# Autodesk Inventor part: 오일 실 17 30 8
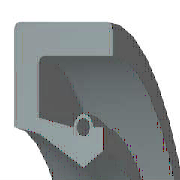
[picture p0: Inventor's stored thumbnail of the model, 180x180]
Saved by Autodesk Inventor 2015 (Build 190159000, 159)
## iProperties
Created: 2012-02
Part Number: 오일 실 17 30 8
Material: 고무
Description: 오일-실
Document SubType Name: Modeling
Standard: KS B 2804
Designer: mduedu
Standards Organization: KS
Language: ko-KR
Size Designation: S - 17 30 8
Categories: <MemberInstance><Categories><Category DisplayName="샤프트 부품" InternalName="7f7aeb1f-a693-4053-b835-cee3144e0d98" Mnemonic="SHFT"><Category DisplayName="실링" Intern
Density: 0.93 g/cm^3
Appearance: 고무 - 검은색 - 버전 1.1
Mass: 1.6913 g
Surface Area: 28.0102 cm^2
Volume: 1.81861 cm^3
IsCustomPart: 1
Author: mduedu
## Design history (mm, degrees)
revolve "본체" stored, may be unused: angle "d17" = 90 deg
revolve "스프링1" stored, may be unused: angle "d18" = 90 deg
body "Solid1"
sketch "스케치1"
  geometry: L1 (0, 15)-(8, 15); L2 (8, 15)-(8, 13.75); L3 (8, 13.75)-(1.75, 13.75); L4 (0, 15)-(0, 10.6); L5 (0, 10.6)-(1.75, 10.25); L6 (1.75, 10.25)-(4.9, 8.5); L7 (4.9, 8.5)-(0, 8.5); L8 (6.3, 9.375)-(6.3, 10.6); L9 (0, 0)-(9.586, 0) reference; L10 (4.9, 8.5)-(6.3, 9.375); L11 (0, 18)-(0, -3) reference; L12 (-1.917, 0)-(11.503, 0) reference; L13 (4.2, 10.6)-(1.75, 11.09); L14 (1.75, 11.09)-(1.75, 13.75); L15 (6.3, 10.6)-(5.6, 10.6); C1 r 0.455 at (4.9, 10.6); A1 r 0.7 centre (4.9, 10.6) between (5.6, 10.6) and (4.2, 10.6)
  constraints: 26 end point, 5 horizontal alignment, 4 perpendicular, 2 centre point, 2 collinear, 2 horizontal, 2 parallel, 2 point on circle, 2 point on line, 2 vertical alignment, 1 coincident
  dimensions: "d0" = 30 diameter of L1 L9 (= SD2); "d1" = 18.75 diameter of L8.start L9 (= ABDM); "d2" = 1.25 distance of L1.end L2.end (computed from SD); "d3" = 0.91 diameter of C1 (= SPDI); "d4" = 1.4 diameter of A1 (= SPDA); "d5" = 17 diameter of L6.end L9 (= NND); "d6" = 20.5 diameter of L5.end L9 (= TKDM); "d7" = 21.2 diameter of L4.end L9 (= HLDM); "d8" = 4.9 distance from line of C1.centre L4 (= SPDST); "d9" = 6.3 distance between parallel lines of L8 L4 (= SDI); "d10" = 8 distance between parallel lines of L2 L4 (= SWDT); "d12" = 1.75 distance between parallel lines of L14 L4 (= SD)
fillet "모깎기1" dims "d11" = 0.3 (= RR)
other parameters: "SD2" = 30 [user parameter; used in 1 equation term], "SWDT" = 8 [user parameter; used in 1 equation term], "RR" = 0.3 [user parameter; used in 1 equation term], "SD" = 1.75 [user parameter; used in 2 equation terms], "NND" = 17 [user parameter; used in 1 equation term], "SPDA" = 1.4 [user parameter; used in 1 equation term], "SPDI" = 0.91 [user parameter; used in 1 equation term], "TKDM" = 20.5 [user parameter; used in 1 equation term], "HLDM" = 21.2 [user parameter; used in 1 equation term], "ABDM" = 18.75 [user parameter; used in 1 equation term], "SDI" = 6.3 [user parameter; used in 1 equation term], "SPDST" = 4.9 [user parameter; used in 1 equation term], "d13" = 0, "d14" = 0, "d15" = 0, "LAB" = 0.35 [user parameter]
